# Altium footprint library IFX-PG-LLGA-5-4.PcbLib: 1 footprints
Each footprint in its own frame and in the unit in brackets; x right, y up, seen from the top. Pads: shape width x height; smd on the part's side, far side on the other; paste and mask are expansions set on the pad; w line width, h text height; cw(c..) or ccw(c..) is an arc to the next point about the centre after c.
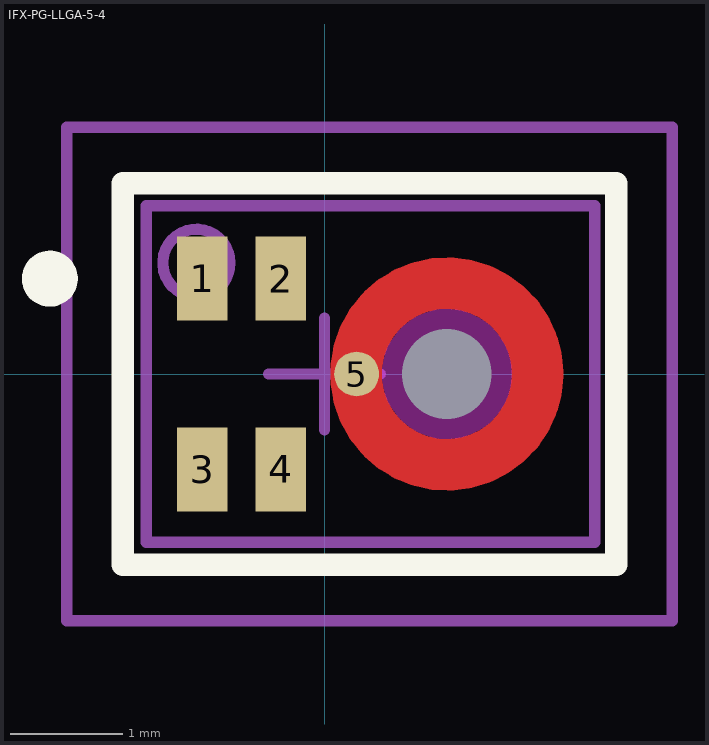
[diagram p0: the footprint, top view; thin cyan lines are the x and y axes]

## IFX-PG-LLGA-5-4 [mm] "Microphone, SMD, 5 pin, 4.00 mm L X 3.00 mm W X 1.30 mm H body"
height 1.3
pads (6):
  rect 0.45x0.75 smd paste-0.3 mask+0: 1(-1.09,0.85) 2(-0.39,0.85) 3(-1.09,-0.85) 4(-0.39,-0.85)
  round 0.4 smd paste-0.2 mask-0.2: 5(0.285,0)
  round 0 hole 0.8 unplated paste+0 mask+0: ""(1.09,0)
Top Layer:
  circle w0.46: c1.09,0 r0.81
Top Overlay:
  circle w0.25: c-2.45,0.85 r0.125
  lines w0.2: -1.8,-1.7 2.6,-1.7 2.6,1.7 -1.8,1.7 -1.8,-1.7
Top Paste:
  lines w0.4: -1.09,-0.975 -1.09,-0.725 ; -1.09,0.725 -1.09,0.975 ; -0.39,-0.975 -0.39,-0.725 ; -0.39,0.725 -0.39,0.975 ; 0.307,-0.166 cw(c1.09,0) 0.307,0.166 ; 0.555,-0.595 ccw(c1.09,0) 0.843,-0.761 ; 0.555,0.595 cw(c1.09,0) 0.843,0.761 ; 1.337,-0.761 ccw(c1.09,0) 1.625,-0.595 ; 1.337,0.761 cw(c1.09,0) 1.625,0.595 ; 1.873,-0.166 ccw(c1.09,0) 1.873,0.166
Keep-Out Layer:
  circle w0.58: c1.09,0 r0.29
M3 (ASY_Text_Top):
  text ".DESIGNATOR" at 0,0 h1.2
M13 (CMP_Body_OTL_Top):
  circle w0.1: c-1.143,0.991 r0.3
  lines w0.1: -1.59,-1.5 2.41,-1.5 2.41,1.5 -1.59,1.5 -1.59,-1.5
M15 (CMP_Courtyard_Top):
  lines w0.1: -0.5,0 0.5,0 ; 0,-0.5 0,0.5 ; -2.3,-2.2 -2.3,2.2 3.1,2.2 3.1,-2.2 -2.3,-2.2
3D body "PG-LLGA-5-4_Z8B00190520_V03_3D.stp": height 1.29, standoff 0, extent -1.59,-1.5 2.41,1.5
